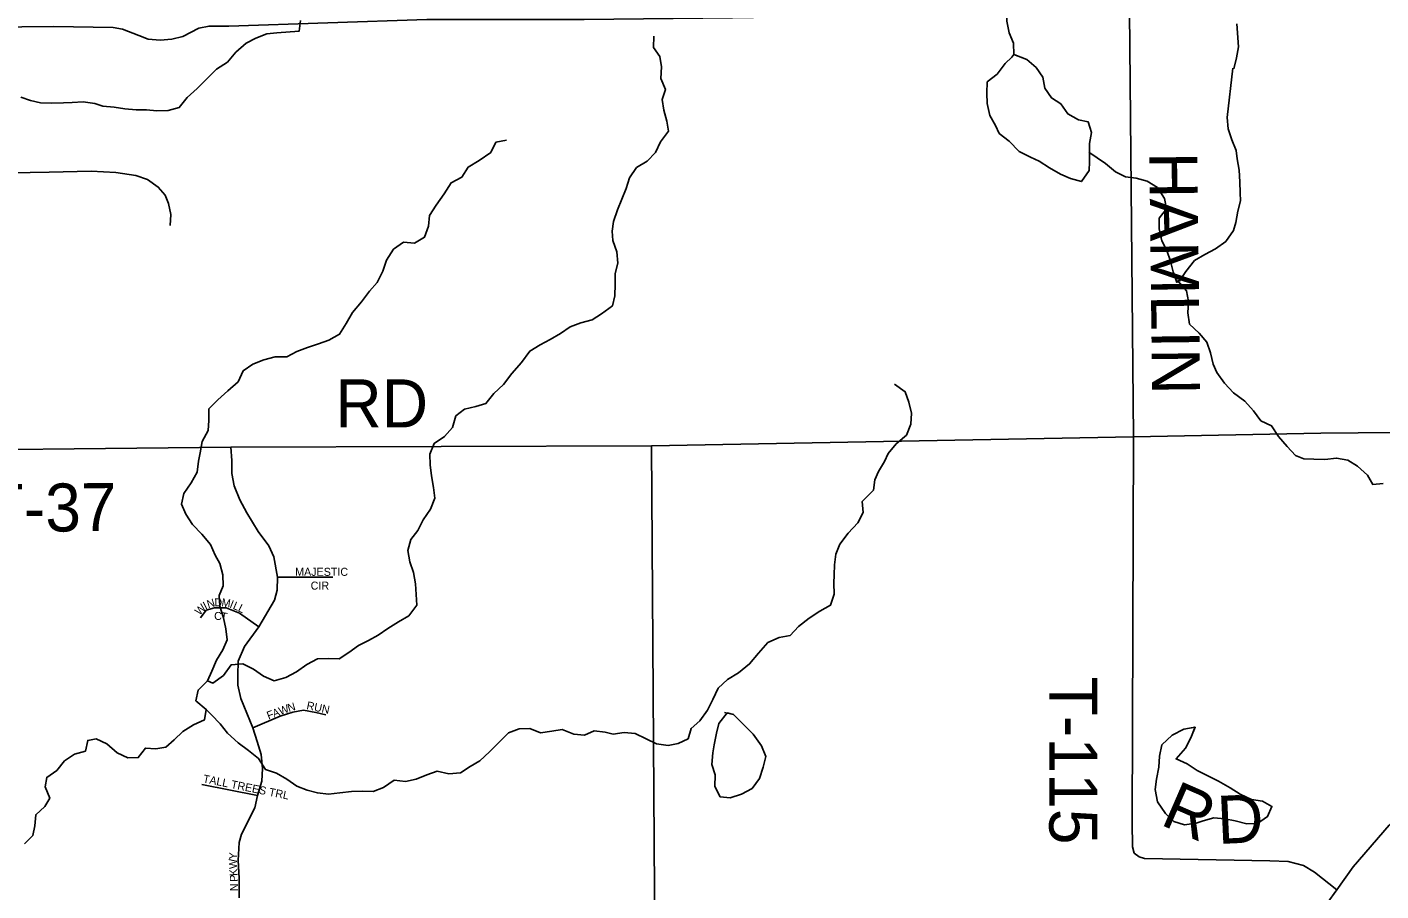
# Model space of a CAD drawing. Extents: x 1985906 to 2277390, y 930619 to 1324581.
# Drawn here: x 2149336 to 2157793, y 1158270 to 1163664 of the extents above; entities that cross this region are included whole.
import ezdxf

# ---------------------------------------------------------------- set-up
doc = ezdxf.new("R2010")
doc.units = 0
for name, color, linetype in [('GM_X_County_Road', 7, 'Continuous'), ('GM_X_Minor_Lake', 7, 'Continuous'), ('GM_X_Minor_River', 7, 'Continuous'), ('GM_X_State_Route', 7, 'Continuous'), ('GM_X_Township_Road', 7, 'Continuous'), ('GM_X_Township_Road_Text', 7, 'Continuous'), ('GM_X_Township_Subdivision', 7, 'Continuous'), ('GM_X_Township_Subdivision_Text', 7, 'Continuous')]:
    doc.layers.add(name, color=color, linetype=linetype)

msp = doc.modelspace()

# ---------------------------------------------------------------- linework, layer by layer
at = {"layer": 'GM_X_County_Road'}
msp.add_lwpolyline([(2147918.6, 1163651.8), (2149501, 1163668.1), (2149873.2, 1163661.1), (2149931.3, 1163651.2), (2150035.4, 1163611.5), (2150093.5, 1163589.6), (2150167.6, 1163581.8), (2150239.6, 1163590), (2150309.6, 1163606.2), (2150409.5, 1163658.6), (2150473.5, 1163670.8), (2150595.6, 1163669.2), (2151834.1, 1163710.8), (2152816.7, 1163711.6), (2153741.8, 1163722), (2156222.5, 1163761.3)], dxfattribs=at)
at = {"layer": 'GM_X_Minor_Lake'}
for points in [[(2155500.2, 1163493.8), (2155487, 1163475.7), (2155447.1, 1163436.7), (2155395.2, 1163370.6), (2155333.3, 1163322.5), (2155331.4, 1163252.4), (2155333.4, 1163186.3), (2155349.4, 1163112.1), (2155385.4, 1163050.1), (2155409.4, 1163000), (2155471.3, 1162952), (2155533.2, 1162887.9), (2155605.2, 1162851.9), (2155659.1, 1162827.9), (2155723, 1162785.8), (2155791, 1162745.8), (2155854.9, 1162719.8), (2155922.8, 1162699.8), (2155970.7, 1162767.9), (2155972.7, 1162824), (2155972.7, 1162938.2)], [(2155499.4, 1163492.6), (2155487, 1163475.7), (2155447.1, 1163436.7), (2155395.2, 1163370.6), (2155333.3, 1163322.5), (2155331.4, 1163252.4), (2155333.4, 1163186.3), (2155349.4, 1163112.1), (2155385.4, 1163050.1), (2155409.4, 1163000), (2155471.3, 1162952), (2155533.2, 1162887.9), (2155605.2, 1162851.9), (2155659.1, 1162827.9), (2155723, 1162785.8), (2155791, 1162745.8), (2155854.9, 1162719.8), (2155922.8, 1162699.8), (2155970.7, 1162767.9), (2155972.7, 1162824), (2155972.7, 1162938.2)], [(2155972.7, 1162938.2), (2155984.6, 1163006.3), (2155964.6, 1163072.4), (2155904.7, 1163084.4), (2155836.8, 1163122.4), (2155794.8, 1163184.5), (2155734.8, 1163222.5), (2155694.9, 1163282.6), (2155680.9, 1163350.7), (2155638.9, 1163412.8), (2155580.9, 1163462.8), (2155496.7, 1163495.2)], [(2155972.7, 1162938.2), (2155984.6, 1163006.3), (2155964.6, 1163072.4), (2155904.7, 1163084.4), (2155836.8, 1163122.4), (2155794.8, 1163184.5), (2155734.8, 1163222.5), (2155694.9, 1163282.6), (2155680.9, 1163350.7), (2155638.9, 1163412.8), (2155580.9, 1163462.8), (2155500.2, 1163493.8)], [(2153729.2, 1158852.6), (2153799.2, 1158874.6), (2153865, 1158910.7), (2153911, 1158972.9), (2153934.9, 1159043), (2153950.9, 1159109.1), (2153924.9, 1159177.2), (2153872.9, 1159249.3), (2153815, 1159305.3), (2153749, 1159371.4), (2153693.1, 1159385.4)], [(2153709.1, 1159381.4), (2153657.2, 1159315.3), (2153643.2, 1159255.2), (2153629.2, 1159183.1), (2153619.3, 1159133), (2153613.3, 1159060.8), (2153635.3, 1158994.8), (2153633.3, 1158922.6), (2153665.3, 1158858.6), (2153729.2, 1158852.6)], [(2153729.2, 1158852.6), (2153799.2, 1158874.6), (2153865, 1158910.7), (2153911, 1158972.9), (2153934.9, 1159043), (2153950.9, 1159109.1), (2153924.9, 1159177.2), (2153872.9, 1159249.3), (2153815, 1159305.3), (2153749, 1159371.4), (2153709.1, 1159381.4)], [(2156632.2, 1159292.2), (2156561.4, 1159280.8), (2156489.5, 1159242.6), (2156425.6, 1159182.5), (2156409.6, 1159112.4), (2156405.7, 1159042.3), (2156391.7, 1158968.1), (2156383.7, 1158904.1), (2156397.8, 1158825.9), (2156447.7, 1158753.8), (2156499.7, 1158703.8), (2156565.6, 1158683.8), (2156639.5, 1158693.8)], [(2156631.7, 1159292.1), (2156561.4, 1159280.8), (2156489.5, 1159242.6), (2156425.6, 1159182.5), (2156409.6, 1159112.4), (2156405.7, 1159042.3), (2156391.7, 1158968.1), (2156383.7, 1158904.1), (2156397.8, 1158825.9), (2156447.7, 1158753.8), (2156499.7, 1158703.8), (2156565.6, 1158683.8), (2156639.5, 1158693.8)], [(2156639.5, 1158693.8), (2156683.4, 1158707.9), (2156749.3, 1158726), (2156817.3, 1158720), (2156883.2, 1158708), (2156955.1, 1158690), (2157023, 1158692.1), (2157084.9, 1158734.1), (2157112.8, 1158798.3), (2157052.9, 1158830.3), (2156985, 1158840.3), (2156915.1, 1158874.3), (2156851.1, 1158914.3), (2156779.2, 1158956.3), (2156707.3, 1158990.4), (2156645.4, 1159022.4), (2156583.4, 1159064.4), (2156513.5, 1159094.4), (2156573.4, 1159162.6), (2156605.3, 1159226.7), (2156633.3, 1159294.8)], [(2156639.5, 1158693.8), (2156683.4, 1158707.9), (2156749.3, 1158726), (2156817.3, 1158720), (2156883.2, 1158708), (2156955.1, 1158690), (2157023, 1158692.1), (2157084.9, 1158734.1), (2157112.8, 1158798.3), (2157052.9, 1158830.3), (2156985, 1158840.3), (2156915.1, 1158874.3), (2156851.1, 1158914.3), (2156779.2, 1158956.3), (2156707.3, 1158990.4), (2156645.4, 1159022.4), (2156583.4, 1159064.4), (2156513.5, 1159094.4), (2156573.4, 1159162.6), (2156605.3, 1159226.7), (2156632.2, 1159292.2)]]:
    msp.add_lwpolyline(points, dxfattribs=at)
at = {"layer": 'GM_X_Minor_River'}
for points in [[(2155499.4, 1163492.6), (2155497.7, 1163564.7), (2155470.3, 1163628.2), (2155456.6, 1163702), (2155459.1, 1163766.2), (2155453.6, 1163834.2), (2155426.2, 1163893.6), (2155424.7, 1163961.7), (2155397.1, 1164029.2), (2155340.7, 1164137.5)], [(2151045.2, 1163706.1), (2151036.8, 1163639.8), (2150897.2, 1163628.5), (2150833.5, 1163623), (2150766.2, 1163595.4), (2150705, 1163564), (2150640.4, 1163508.4), (2150587.9, 1163445.1), (2150519, 1163401.4), (2150460.5, 1163343.9), (2150398, 1163280.4), (2150335.4, 1163224.9), (2150286.9, 1163161.6), (2150217.5, 1163144), (2150147.6, 1163142.4), (2150081.6, 1163146.9), (2150017.7, 1163147.4), (2149947.6, 1163153.8), (2149879.5, 1163164.2), (2149809.5, 1163170.6), (2149759.2, 1163187.5), (2149687, 1163197.8), (2149617.2, 1163194.2), (2149563.4, 1163191), (2149489.5, 1163189.2), (2149419.6, 1163191.6), (2149357.3, 1163206.2), (2149296.9, 1163226.9)], [(2156892.8, 1163685.2), (2156904.1, 1163541.2), (2156891.7, 1163472.8), (2156875.3, 1163404.3)], [(2150463.3, 1159581.8), (2150495.6, 1159568.5), (2150562.4, 1159616.1), (2150610.8, 1159681.3), (2150684.5, 1159689.1), (2150751.2, 1159654.5), (2150812.1, 1159611.9), (2150880.7, 1159581.4), (2150952.1, 1159603.1), (2151019.1, 1159638.7), (2151084, 1159684.3), (2151151.1, 1159719.9), (2151218.9, 1159721.4), (2151284.9, 1159719), (2151345.9, 1159758.4), (2151406.8, 1159801.9), (2151470, 1159833.4), (2151529.1, 1159866.9), (2151590, 1159908.3), (2151657, 1159949.9), (2151720, 1159987.5), (2151770.4, 1160054.8), (2151766.9, 1160120.8), (2151763.3, 1160188.8), (2151749.7, 1160258.6), (2151726.2, 1160326.2), (2151714.6, 1160396), (2151733, 1160464.6), (2151777.6, 1160521.7), (2151810, 1160588.6), (2151856.4, 1160653.7), (2151882.8, 1160722.5), (2151875.2, 1160790.4), (2151861.6, 1160862.2), (2151854.1, 1160930.1), (2151852.5, 1160998.2), (2151878.9, 1161064.9), (2151943.8, 1161108.5), (2151994.4, 1161163.8), (2152014.7, 1161236.4), (2152069.7, 1161277.7), (2152139.2, 1161295.3), (2152202.6, 1161314.8), (2152251.1, 1161376.1), (2152311.7, 1161433.6), (2152364.1, 1161500.9), (2152424.4, 1161570.4), (2152476.7, 1161641.7), (2152541.7, 1161681.3), (2152604.8, 1161712.8), (2152667.9, 1161750.3), (2152728.8, 1161791.8), (2152796.1, 1161817.4), (2152865.6, 1161837), (2152924.6, 1161874.4), (2152993.4, 1161924.1), (2153007.9, 1161986.6), (2153010.2, 1162058.7), (2153010.7, 1162126.8), (2153027.2, 1162191.3), (2153019.6, 1162261.3), (2152995.9, 1162332.8), (2152990.6, 1162390.8), (2152999.2, 1162451.1), (2153025.5, 1162523.9), (2153078.3, 1162657.3), (2153098.8, 1162723.9), (2153143.2, 1162787), (2153210.2, 1162826.6), (2153260.9, 1162881.9), (2153293.3, 1162948.8), (2153343.7, 1163014), (2153332.2, 1163077.9), (2153314.7, 1163145.6), (2153303.2, 1163211.4), (2153323.7, 1163274), (2153294.2, 1163343.4), (2153298.5, 1163415.6), (2153289, 1163481.5), (2153249.8, 1163536.7), (2153252.1, 1163606.9)], [(2156522.3, 1162081.9), (2156534.4, 1162078.2), (2156574.9, 1162139.2), (2156629.3, 1162206.6), (2156694.3, 1162244.2), (2156759.4, 1162279.7), (2156824.3, 1162325.3), (2156872.6, 1162394.5), (2156887.4, 1162445), (2156899.8, 1162515.4), (2156916.2, 1162579.8), (2156915.1, 1162629.9), (2156911.5, 1162697.9), (2156907.9, 1162770), (2156896.2, 1162841.8), (2156889.1, 1162893.8), (2156861.5, 1162961.2), (2156840, 1163028.8), (2156832.4, 1163100.8), (2156868.5, 1163408.5)], [(2152330.5, 1162958.5), (2152264.9, 1162945), (2152232.4, 1162882.1), (2152159.7, 1162832.4), (2152090.8, 1162790.7), (2152052.3, 1162727.7), (2151985.2, 1162692.1), (2151940.8, 1162623), (2151892.6, 1162551.7), (2151850.1, 1162488.6), (2151843.7, 1162420.4), (2151819.3, 1162351.7), (2151756.2, 1162316.2), (2151688.2, 1162320.6), (2151625.3, 1162277.1), (2151580.9, 1162209.9), (2151558.6, 1162139.3), (2151522.2, 1162070.4), (2151475.6, 1162015.2), (2151425.2, 1161947.9), (2151368.8, 1161882.5), (2151330.5, 1161813.5), (2151288.1, 1161746.4), (2151221.1, 1161708.8), (2151157.6, 1161687.3), (2151088.3, 1161663.7), (2151021, 1161638.1), (2150957.9, 1161604.6), (2150886, 1161604.9), (2150814.5, 1161587.2), (2150747.2, 1161559.6), (2150686.3, 1161518.1), (2150653.9, 1161449.3), (2150589.3, 1161393.7), (2150528.7, 1161336.2), (2150472.1, 1161280.8), (2150471.7, 1161208.7), (2150467.2, 1161144.5), (2150430.8, 1161077.5), (2150418.5, 1161005.1), (2150407.7, 1160954.8), (2150399.3, 1160884.5), (2150360.9, 1160819.5), (2150316.5, 1160752.3), (2150300.1, 1160685.8), (2150327.5, 1160622.4), (2150368.9, 1160559.2), (2150428.2, 1160498.5), (2150481.6, 1160433.6), (2150511.1, 1160366.2), (2150540.3, 1160314.8), (2150559.9, 1160243.1), (2150561.5, 1160175), (2150536.9, 1160114.4), (2150540.4, 1160048.3), (2150564.1, 1159974.8), (2150577.6, 1159907), (2150585.2, 1159839), (2150558.7, 1159776.3), (2150520.2, 1159711.3), (2150489.9, 1159642.5), (2150463.3, 1159581.8), (2150404.7, 1159524.3), (2150390.3, 1159457.9), (2150455.4, 1159403.3), (2150445, 1159338.9), (2150375.8, 1159307.3), (2150308.9, 1159265.7), (2150256.1, 1159214.4), (2150203.3, 1159167.1), (2150141.6, 1159157.6), (2150075.6, 1159162.1), (2150031, 1159103), (2149965.2, 1159101.5), (2149898.6, 1159132), (2149835.4, 1159188.6), (2149768.8, 1159219.1), (2149715.1, 1159209.9), (2149700.6, 1159143.4), (2149633.2, 1159123.8), (2149570.2, 1159082.3), (2149521.7, 1159023.1), (2149458.8, 1158979.6), (2149450.2, 1158919.3), (2149477.7, 1158849.8), (2149447, 1158797), (2149390.3, 1158745.6), (2149383.9, 1158677.3), (2149371.3, 1158616.9), (2149320.6, 1158563.7)], [(2156522.3, 1162081.9), (2156518.6, 1162069.8), (2156495.1, 1162135.4), (2156479.6, 1162203.1), (2156456.1, 1162268.7), (2156424.8, 1162330.1), (2156409.1, 1162403.8), (2156407.5, 1162471.9), (2156454.1, 1162529.1), (2156440.6, 1162594.9), (2156397.1, 1162662), (2156332.3, 1162702.6), (2156264, 1162721), (2156197.9, 1162729.5), (2156135.3, 1162760.1), (2156072.2, 1162812.7), (2155969.6, 1162883.4)], [(2157807.6, 1160813.5), (2157743.8, 1160808), (2157710.5, 1160867.3), (2157647.3, 1160921.9), (2157586.6, 1160960.6), (2157516.4, 1160973), (2157442.7, 1160963.3), (2157374.8, 1160965.7), (2157310.8, 1160968.3), (2157260.4, 1160989.1), (2157207.2, 1161046), (2157153.8, 1161108.9), (2157110.4, 1161174), (2157043.7, 1161206.5), (2156996.4, 1161267.5), (2156943.1, 1161328.4), (2156872, 1161380.8), (2156816.6, 1161441.6), (2156769.2, 1161506.6), (2156746, 1161560.2), (2156728.4, 1161629.9), (2156706.9, 1161697.5), (2156657.7, 1161752.5), (2156598.5, 1161809.2), (2156586.9, 1161881.1), (2156591.2, 1161951.3), (2156579.7, 1162017.1), (2156522.3, 1162081.9)], [(2150455.4, 1159403.3), (2150488.2, 1159370), (2150541.4, 1159313.1), (2150588.6, 1159256.1), (2150653.9, 1159195.5), (2150719, 1159146.9), (2150782, 1159098.3), (2150825.5, 1159029.2), (2150893.9, 1159006.7), (2150958.7, 1158968.2), (2151021.6, 1158923.6), (2151086.1, 1158899), (2151150.4, 1158882.4), (2151218.5, 1158874), (2151290.2, 1158883.7), (2151361.9, 1158891.3), (2151429.7, 1158892.9), (2151497.7, 1158890.5), (2151563, 1158916), (2151629.8, 1158961.6), (2151699.9, 1158953.2), (2151767.4, 1158968.8), (2151832.8, 1158994.4), (2151898.1, 1159017.9), (2151970.4, 1159001.6), (2152044.1, 1159007.3), (2152103.1, 1159046.7), (2152164.2, 1159082.2), (2152224.8, 1159139.7), (2152281.4, 1159195.1), (2152343.9, 1159256.6), (2152409.2, 1159282.2), (2152477.1, 1159283.8), (2152543.6, 1159257.2), (2152615.2, 1159268.9), (2152678.9, 1159278.4), (2152751.4, 1159250), (2152817.5, 1159243.6), (2152878.8, 1159269), (2152946.8, 1159262.6), (2152997.1, 1159249.7), (2153066.7, 1159259.3), (2153134.8, 1159252.9), (2153203.4, 1159220.4), (2153268.1, 1159187.9), (2153340.2, 1159177.5), (2153403.8, 1159191), (2153465, 1159220.5), (2153485.5, 1159285), (2153538.3, 1159332.3), (2153586.7, 1159399.6), (2153619.1, 1159466.4), (2153653.4, 1159537.3), (2153712.1, 1159590.8), (2153781, 1159632.5), (2153849.6, 1159688.1), (2153906, 1159755.6), (2153964.4, 1159821), (2154033.6, 1159852.7), (2154103.1, 1159866.3), (2154155.8, 1159921.6), (2154222.5, 1159973.2), (2154289.4, 1160016.8), (2154354.4, 1160054.4), (2154378.8, 1160123.1), (2154375.2, 1160193.1), (2154378, 1160243.3), (2154380.5, 1160307.4), (2154389, 1160373.8), (2154413.5, 1160436.4), (2154465.9, 1160503.8), (2154526.3, 1160569.2), (2154558.7, 1160634.1), (2154553.2, 1160702.1), (2154623.5, 1160771.8), (2154631.9, 1160838.1), (2154654.7, 1160888.8), (2154693.2, 1160951.8), (2154716, 1161002.4), (2154764.6, 1161061.6), (2154829.2, 1161117.2), (2154857.5, 1161185.9), (2154862, 1161254.2), (2154844.4, 1161321.9), (2154821, 1161387.4), (2154754, 1161434)]]:
    msp.add_lwpolyline(points, dxfattribs=at)
at = {"layer": 'GM_X_State_Route'}
msp.add_lwpolyline([(2157143.5, 1156308.8), (2157143.5, 1156309.4), (2157135.7, 1156657.1), (2157144.7, 1157019.9), (2157190, 1157482.9), (2157238.7, 1157725.3), (2157335.4, 1157995.7), (2157458.1, 1158193.8), (2157518.8, 1158278.2), (2157620.8, 1158419.9), (2157845.5, 1158680), (2158010.5, 1158844.4), (2158092.3, 1158925.9), (2158776.6, 1159653.8), (2160363, 1161353.5), (2160406, 1161399.6), (2160857.2, 1161870.9), (2161310.1, 1162347.2), (2161802.1, 1162775.3), (2162199.7, 1163097.7), (2162513.7, 1163328), (2162520.8, 1163333.9)], dxfattribs=at)
at = {"layer": 'GM_X_Township_Road'}
for points in [[(2156247.6, 1161104.9), (2156222.5, 1163761.3), (2156216.5, 1165240.9), (2156218.2, 1165349.2), (2156210, 1165413.4), (2156187.8, 1165477.4)], [(2153236.1, 1161050.3), (2156247.6, 1161104.9)], [(2157518.8, 1158278.2), (2157377.5, 1158387.4), (2157309.4, 1158429.3), (2157213.3, 1158453.1), (2157099.2, 1158458.8), (2156316.8, 1158472.6), (2156282.7, 1158482.5), (2156252.6, 1158506.5), (2156240.5, 1158546.6), (2156240.1, 1158696.9), (2156247.6, 1161104.9)], [(2156247.6, 1161104.9), (2157418.2, 1161128.3), (2159285.2, 1161145.5), (2159664.1, 1161151.6), (2159666.2, 1161151.6)], [(2147126, 1161008.8), (2148259.3, 1161016.5), (2150608.6, 1161041.2), (2153236.1, 1161050.3)], [(2153272.3, 1155797.3), (2153236.1, 1161050.3)]]:
    msp.add_lwpolyline(points, dxfattribs=at)
at = {"layer": 'GM_X_Township_Subdivision'}
for points in [[(2147713.6, 1163031.6), (2147787.8, 1163013.7), (2147849.8, 1163007.8), (2148001.9, 1163022.3), (2148072, 1163020.5), (2148152, 1163004.7), (2148318.3, 1162926.9), (2148552.8, 1162821.4), (2148646.9, 1162795.6), (2148903.1, 1162760.2), (2149117.3, 1162752.8), (2149473.4, 1162757.8), (2149737.6, 1162764.6), (2149891.7, 1162757), (2150015.8, 1162737.3), (2150087.9, 1162713.4), (2150156.1, 1162665.5), (2150198.2, 1162615.5), (2150220.4, 1162563.4), (2150234.6, 1162493.3), (2150230.8, 1162425.1)], [(2150661.1, 1158226.7), (2150661.1, 1158350.6), (2150655.4, 1158460.5), (2150661.1, 1158573.1), (2150675.2, 1158623.9), (2150759.6, 1158790), (2150776.6, 1158866.1), (2150801.9, 1158956.2), (2150807.5, 1159035.1), (2150799.1, 1159122.4), (2150773.7, 1159204.1), (2150745.6, 1159288.6), (2150672.3, 1159471.7), (2150652.6, 1159556.2), (2150652.6, 1159618.2), (2150655.4, 1159705.5), (2150694.9, 1159795.6), (2150785, 1159919.5), (2150880.8, 1160085.7), (2150897.7, 1160147.7), (2150900.5, 1160229.4), (2150876.8, 1160357.3), (2150847.2, 1160426.2), (2150780.8, 1160514.7), (2150709.5, 1160630.4), (2150665.2, 1160711.6), (2150630.7, 1160800.1), (2150616, 1160876.4), (2150616, 1160957.6), (2150608.6, 1161041.2)], [(2150900.5, 1160229.4), (2151246.9, 1160229.4)], [(2150418.8, 1159975.9), (2150455.4, 1160023.7), (2150506.2, 1160037.8), (2150579.4, 1160037.8), (2150663.9, 1160004), (2150785, 1159919.5)], [(2150745.6, 1159288.6), (2150917.4, 1159361.8), (2150996.3, 1159387.2), (2151063.9, 1159398.4), (2151139.9, 1159384.4), (2151201.9, 1159370.3)], [(2150427.5, 1158935.1), (2150776.6, 1158866.1)]]:
    msp.add_lwpolyline(points, dxfattribs=at)

# ---------------------------------------------------------------- texts
at = {"layer": 'GM_X_Township_Road_Text'}
for s, rotation, p in [('HAMLIN', 270.68849, (2156346.2, 1162883.1)), ('RD', 0.00001, (2151261.7, 1161164.8)), ('T-37', 0.70694, (2149072.5, 1160508.6)), ('T-115', 270, (2155721.8, 1159608.1)), ('R', 336.46471, (2156406.7, 1158687.8)), ('D', 2.65714, (2156776.1, 1158563))]:
    msp.add_text(s, height=300, rotation=rotation, dxfattribs=at).set_placement(p)
at = {"layer": 'GM_X_Township_Subdivision_Text'}
for s, rotation, p in [('MAJESTIC', 0.00001, (2151010.9, 1160237.9)), ('CIR', 0.00001, (2151107.7, 1160151.8)), ('W', 45.3566, (2150413.8, 1159987.8)), ('I', 26.31092, (2150450.4, 1160025.9)), ('N', 16.83114, (2150468.1, 1160034.9)), ('D', 1.35508, (2150506.7, 1160047.1)), ('M', 351.68446, (2150548.5, 1160048.2)), ('I', 338.09306, (2150597.7, 1160041.4)), ('L', 336.9808, (2150617.9, 1160033.3)), ('L', 333.37387, (2150649.5, 1160019.9)), ('C', 359.44139, (2150504.7, 1159962.6)), ('T', 351.0856, (2150542.4, 1159962.4)), ('F', 20.57843, (2150844.6, 1159339.6)), ('A', 20.59467, (2150877.6, 1159352)), ('W', 20.58359, (2150918.8, 1159367.5)), ('N', 16.60294, (2150971.4, 1159387.3)), ('RUN', 347.90578, (2151078.8, 1159406.1)), ('TALL TREES TRL', 348.58946, (2150431.9, 1158948.5)), ('W', 92.74152, (2150649.2, 1158409)), ('Y', 86.04052, (2150646.4, 1158464.6)), ('K', 94.26958, (2150652.4, 1158365.5)), ('P', 91.97719, (2150653.7, 1158328.1)), ('N', 90.01537, (2150653.8, 1158269))]:
    msp.add_text(s, height=50, rotation=rotation, dxfattribs=at).set_placement(p)

doc.saveas('drawing.dxf')
